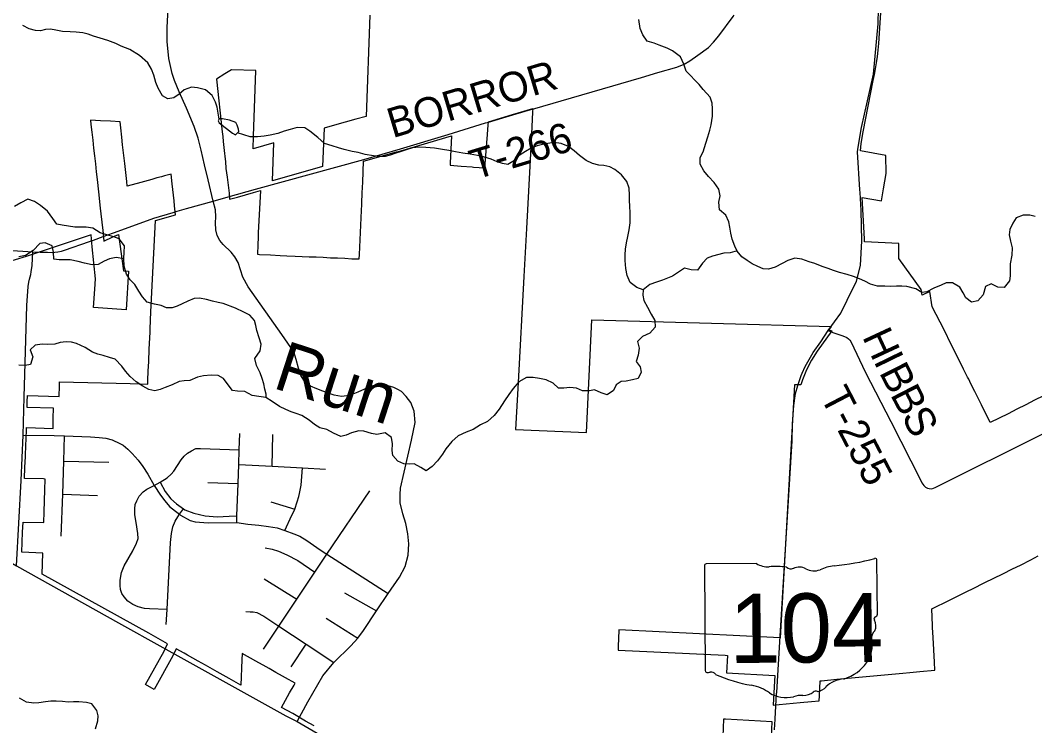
# Model space of a CAD drawing. Extents: x 114843 to 284848, y 317643 to 566895.
# Drawn here: x 189485 to 199714, y 338344 to 345452 of the extents above; entities that cross this region are included whole.
import ezdxf

# ---------------------------------------------------------------- set-up
doc = ezdxf.new("R2010")
doc.units = 0
for name, color, linetype in [('GM_X_City_Street', 7, 'Continuous'), ('GM_X_Corporation', 7, 'Continuous'), ('GM_X_Minor_Lake', 7, 'Continuous'), ('GM_X_Minor_River', 7, 'Continuous'), ('GM_X_Minor_River_Text', 7, 'Continuous'), ('GM_X_State_Location', 7, 'Continuous'), ('GM_X_State_Route', 7, 'Continuous'), ('GM_X_State_Shield', 7, 'Continuous'), ('GM_X_Township_Road', 7, 'Continuous'), ('GM_X_Township_Road_Text', 7, 'Continuous')]:
    doc.layers.add(name, color=color, linetype=linetype)

msp = doc.modelspace()

# ---------------------------------------------------------------- linework, layer by layer
at = {"layer": 'GM_X_City_Street'}
for p, q in [((189513, 341272), (189827, 341267)), ((192026, 340959), (192030, 341279)), ((189925, 341008), (190377, 340998)), ((191376, 340796), (191681, 340785)), ((189914, 340676), (190265, 340663)), ((192577, 340073), (193008, 340709)), ((192011, 340599), (192252, 340526)), ((191944, 339825), (192273, 339619)), ((192755, 339682), (193078, 339500)), ((192570, 339426), (192887, 339225)), ((192218, 338936), (192369, 339165))]:
    msp.add_line(p, q, dxfattribs=at)
for points in [[(191430, 343630), (191381, 343845), (191343, 343996), (191310, 344143), (191278, 344263), (191238, 344381), (191160, 344565), (191087, 344730), (191039, 344846), (191016, 344917), (190982, 345066), (190965, 345240), (190965, 345379), (190980, 345638)], [(192276, 338385), (192386, 338584), (192535, 338846), (192646, 338980), (192818, 339147), (192887, 339225), (192945, 339302), (193078, 339500), (193194, 339675), (193309, 339839), (193366, 339949), (193396, 340063), (193404, 340178), (193394, 340278), (193371, 340382), (193341, 340479), (193317, 340590), (193314, 340672), (193320, 340737), (193430, 341222), (193465, 341400), (193457, 341513), (193422, 341602), (193377, 341660), (193328, 341712), (193291, 341731), (193250, 341753), (193193, 341769), (193137, 341777), (193076, 341777), (193017, 341762), (192888, 341705), (192805, 341671), (192723, 341660), (192650, 341676), (192535, 341716), (192476, 341738), (192410, 341764), (192357, 341806), (192313, 341871), (192290, 341947), (192267, 342035), (192242, 342111), (192122, 342287), (191784, 342767), (191730, 342862), (191682, 343013), (191648, 343070), (191611, 343114), (191531, 343194), (191498, 343232), (191470, 343284), (191458, 343342), (191454, 343411), (191457, 343473), (191453, 343542), (191430, 343630)], [(189357, 343135), (189610, 343119)], [(189827, 341267), (189931, 341266), (190194, 341253), (190280, 341248), (190346, 341240), (190413, 341223), (190490, 341188), (190521, 341169), (190568, 341129), (190614, 341086), (190672, 341019), (190722, 340957), (190771, 340880), (190836, 340765), (190900, 340667), (190942, 340611), (190991, 340551), (191050, 340505), (191091, 340474), (191102, 340465), (191199, 340413), (191250, 340399), (191380, 340389), (191668, 340390), (191781, 340374), (191889, 340363), (191987, 340351), (192076, 340336), (192154, 340310), (192244, 340278), (192305, 340253), (192376, 340209), (192510, 340116), (192577, 340073), (193194, 339675)], [(189898, 340254), (189914, 340676), (189925, 341008), (189931, 341266)], [(191668, 340390), (191670, 340459), (191681, 340785), (191687, 340977), (191692, 341125), (191698, 341287)], [(190836, 340765), (190895, 340799), (190966, 340841), (191005, 340877), (191034, 340910), (191108, 341024), (191136, 341059), (191171, 341090), (191210, 341114), (191256, 341137), (191302, 341137), (191692, 341125)], [(191687, 340977), (192026, 340959), (192330, 340942), (192561, 340930)], [(192154, 340310), (192223, 340465), (192246, 340510), (192252, 340526), (192278, 340599), (192292, 340655), (192301, 340684), (192318, 340768), (192330, 340942)], [(190965, 339516), (190787, 339520), (190737, 339526), (190673, 339542), (190620, 339566), (190569, 339600), (190531, 339642), (190510, 339675), (190496, 339717), (190491, 339755), (190493, 339811), (190506, 339887), (190534, 339954), (190619, 340105), (190658, 340184), (190672, 340230), (190670, 340282), (190654, 340391), (190640, 340469), (190639, 340528), (190644, 340572), (190659, 340611), (190683, 340656), (190723, 340699), (190760, 340726), (190836, 340765)], [(190895, 340799), (190945, 340705), (191002, 340631), (191059, 340581), (191130, 340530), (191144, 340519), (191235, 340484), (191350, 340458), (191470, 340450), (191592, 340455), (191670, 340459)], [(190957, 339362), (190965, 339516), (191001, 340190), (191010, 340280), (191024, 340347), (191048, 340405), (191074, 340450), (191091, 340474), (191130, 340530)], [(191955, 340136), (192026, 340123), (192088, 340101), (192171, 340066), (192284, 340008), (192456, 339892)], [(191937, 339116), (192091, 339347), (192273, 339619), (192456, 339892), (192577, 340073)], [(191760, 339493), (191804, 339492), (191834, 339491), (191870, 339485), (191940, 339447), (192091, 339347), (192369, 339165), (192646, 338980)]]:
    msp.add_lwpolyline(points, dxfattribs=at)
at = {"layer": 'GM_X_Corporation'}
for points in [[(199802, 341667), (199713, 341623), (199623, 341578), (199534, 341533), (199445, 341488), (199355, 341443), (199266, 341399), (199177, 341577), (199109, 341711), (199071, 341788), (199048, 341835), (199042, 341845), (199036, 341857), (198997, 341936), (198934, 342061), (198872, 342184), (198801, 342332), (198678, 342565), (198655, 342718), (198578, 342681), (198570, 342738), (198345, 343051), (198343, 343203), (197998, 343220), (197997, 343251), (197983, 343488), (197973, 343666), (198168, 343633), (198188, 343753), (198215, 343909), (198213, 344091), (197956, 344135), (197963, 344212), (197984, 344327), (198086, 344846), (198097, 344905), (198108, 344964), (198118, 345023), (198128, 345087), (198136, 345152), (198142, 345217), (198246, 346829)], [(193009, 345503), (192971, 344484), (192867, 344455), (192760, 344425), (192654, 344395), (192549, 344365), (192545, 344288), (192532, 343979), (192028, 343835), (192040, 344217), (191936, 344187), (191832, 344158), (191837, 344283), (191859, 344946), (191616, 344953), (191548, 344911), (191462, 344858), (191521, 344328), (191526, 344281), (191532, 344231), (191542, 344141), (191552, 344051), (191554, 344030), (191559, 343960), (191572, 343871), (191587, 343736), (191590, 343709), (191596, 343648), (191676, 343671), (191837, 343717), (191906, 343736), (191885, 343311), (191884, 343280), (191879, 343176), (191876, 343108), (191876, 343094), (191898, 343093), (192008, 343088), (192104, 343083), (192174, 343080), (192258, 343076), (192328, 343073), (192398, 343070), (192468, 343067), (192538, 343064), (192613, 343060), (192683, 343057), (192758, 343054), (192828, 343050), (192902, 343047), (192904, 343091), (192908, 343165), (192911, 343239), (192915, 343313), (192918, 343387), (192922, 343461), (192925, 343535), (192928, 343596), (192928, 343610), (192933, 343713), (192938, 343821), (192945, 344031), (193279, 344125), (193288, 344127), (193504, 344189), (193832, 344289), (193819, 344013), (193818, 343991), (193931, 343983), (194042, 343974), (194055, 343973), (194168, 343964), (194196, 344300), (194203, 344397), (194206, 344430), (194449, 344503), (194653, 344562), (194651, 344528), (194640, 344303), (194622, 343981), (194589, 343355), (194562, 342869), (194505, 341802), (194480, 341329), (195193, 341299), (195248, 342433), (197662, 342368), (197637, 342332), (197668, 342323), (197521, 342119), (197462, 342027), (197413, 341930), (197392, 341880), (197373, 341828), (197356, 341777), (197293, 341780), (197146, 339230), (195521, 339310), (195521, 339310), (195518, 339220), (195515, 339150), (195513, 339106), (196591, 339053), (196615, 339051), (196605, 338878), (197094, 338850), (197091, 338791), (197081, 338616), (197077, 338550), (197138, 338556), (197349, 338577), (197462, 338587), (197541, 338595), (197544, 338646), (197552, 338795), (197564, 338796), (197719, 338811), (197825, 338821), (197866, 338825), (198124, 338850), (198274, 338864), (198383, 338874), (198453, 338881), (198555, 338891), (198706, 338903), (198702, 338983), (198695, 339107), (198689, 339232), (198684, 339332), (198683, 339355), (198677, 339522), (198856, 339610), (199035, 339698), (199086, 339723), (199212, 339786), (199392, 339874), (199491, 339923), (199570, 339963), (199674, 340016), (199749, 340054)], [(192448, 338343), (192362, 338391), (192232, 338466), (192119, 338528), (192201, 338674), (192246, 338753), (192256, 338772), (192158, 338827), (192130, 338843), (192062, 338881), (191995, 338919), (191963, 338936), (191859, 338994), (191723, 339071), (191720, 339008), (191710, 338753), (191685, 338767), (191592, 338819), (191470, 338887), (191352, 338953), (191280, 338993), (191172, 339054), (191136, 339074), (191057, 339118), (191022, 339048), (190834, 338709), (190746, 338758), (190935, 339096), (190969, 339168), (190780, 339275), (189705, 339872), (189712, 340083), (189502, 340092), (189505, 340193), (189509, 340294), (189513, 340395), (189723, 340390), (189726, 340500), (189730, 340610), (189734, 340720), (189737, 340829), (189719, 340830), (189528, 340835), (189532, 340945), (189536, 341055), (189540, 341178), (189544, 341225), (189547, 341337), (189547, 341347), (189815, 341340), (189818, 341443), (189821, 341543), (189554, 341550), (189555, 341606), (189557, 341670), (189877, 341662), (189881, 341768), (189882, 341809), (190594, 341792), (190770, 341787), (190772, 341825), (190776, 341915), (190780, 342014), (190786, 342137), (190793, 342308), (190795, 342344), (190803, 342514), (190847, 343435), (191050, 343493), (191044, 343553), (191041, 343581), (191035, 343634), (191016, 343803), (191005, 343903), (190940, 343885), (190909, 343876), (190863, 343863), (190812, 343849), (190736, 343827), (190699, 343817), (190564, 343779), (190558, 343829), (190538, 344009), (190526, 344118), (190517, 344198), (190509, 344276), (190498, 344367), (190492, 344429), (190395, 344434), (190294, 344440), (190193, 344446), (190198, 344403), (190207, 344324), (190213, 344271), (190216, 344244), (190224, 344165), (190233, 344085), (190242, 344006), (190251, 343926), (190260, 343847), (190273, 343724), (190292, 343558), (190314, 343360), (190316, 343338), (190328, 343226), (190419, 343270), (190477, 343292), (190525, 342927), (190576, 342925), (190553, 342533), (190224, 342557), (190236, 342742), (190244, 342847), (190211, 343169), (190199, 343289), (189545, 343072), (189322, 343005)], [(197059, 338235), (197068, 338382), (196595, 338408), (196576, 338409), (196569, 338234)]]:
    msp.add_lwpolyline(points, dxfattribs=at)
at = {"layer": 'GM_X_Minor_Lake'}
for points in [[(191688, 344331), (191686, 344355), (191672, 344396), (191660, 344422), (191596, 344446), (191524, 344460), (191492, 344460), (191480, 344438), (191490, 344418), (191626, 344315), (191656, 344299)], [(191656, 344299), (191688, 344331)]]:
    msp.add_lwpolyline(points, dxfattribs=at)
at = {"layer": 'GM_X_Minor_River'}
for points in [[(196399, 344213), (196417, 344279), (196438, 344345), (196450, 344399), (196464, 344487), (196466, 344559), (196460, 344618), (196440, 344678), (196372, 344756), (196330, 344806), (196198, 344939), (196174, 345009), (196142, 345083), (196063, 345145), (196009, 345171), (195927, 345203), (195875, 345220), (195806, 345242), (195763, 345304), (195735, 345370), (195721, 345460)], [(191490, 344456), (191470, 344576), (191455, 344626), (191421, 344695), (191351, 344751), (191273, 344771), (191213, 344777), (191137, 344753), (191086, 344709), (191032, 344671), (190974, 344661), (190920, 344691), (190876, 344767), (190852, 344826), (190833, 344898), (190807, 344960), (190771, 345022), (190687, 345098), (190591, 345157), (190503, 345193), (190447, 345217), (190369, 345247), (190289, 345273), (190223, 345293), (190169, 345312), (190115, 345326), (190049, 345334), (189987, 345336), (189909, 345340), (189845, 345352), (189791, 345364), (189739, 345358), (189688, 345346), (189638, 345348), (189574, 345366), (189510, 345399)], [(195765, 342737), (195703, 342759), (195633, 342811), (195605, 342879), (195591, 342951), (195585, 343031), (195585, 343090), (195589, 343146), (195599, 343208), (195611, 343274), (195623, 343342), (195634, 343410), (195634, 343514), (195632, 343577), (195628, 343639), (195628, 343689), (195624, 343759), (195600, 343827), (195548, 343895), (195480, 343949), (195428, 343976), (195370, 343990), (195318, 343992), (195256, 344010), (195190, 344040), (195124, 344090), (195070, 344138), (195012, 344181), (194938, 344209), (194866, 344219), (194804, 344211), (194750, 344201), (194696, 344187), (194636, 344163), (194578, 344131), (194514, 344089), (194450, 344029), (194400, 343999), (194346, 344009), (194292, 344027), (194232, 344051), (194154, 344076), (194096, 344090), (194020, 344102), (193947, 344114), (193875, 344128), (193807, 344140), (193741, 344150), (193661, 344162), (193573, 344171), (193507, 344173), (193439, 344167), (193385, 344151), (193327, 344131), (193273, 344113), (193215, 344093), (193163, 344079), (193099, 344079), (193047, 344087), (192963, 344101), (192891, 344119), (192833, 344131), (192751, 344150), (192693, 344168), (192631, 344186), (192551, 344212), (192485, 344270), (192405, 344334), (192353, 344369), (192277, 344373), (192207, 344353), (192147, 344335), (192083, 344311), (192006, 344295), (191944, 344285), (191876, 344279), (191804, 344279), (191676, 344319)], [(199717, 343475), (199665, 343487), (199598, 343487), (199528, 343461), (199492, 343409), (199464, 343345), (199456, 343289), (199470, 343227), (199486, 343159), (199482, 343084), (199466, 342998), (199465, 342876), (199461, 342826), (199407, 342760), (199343, 342762), (199275, 342796), (199219, 342768), (199193, 342686), (199139, 342626), (199075, 342612), (199019, 342654), (198991, 342706), (198957, 342764), (198883, 342805), (198821, 342805), (198771, 342783), (198695, 342753), (198627, 342717), (198575, 342709), (198515, 342745), (198425, 342769), (198373, 342773), (198320, 342773), (198258, 342771), (198204, 342773), (198130, 342774), (198058, 342794), (198000, 342822), (197946, 342848), (197886, 342870), (197824, 342890), (197744, 342912), (197684, 342931), (197630, 342951), (197570, 342971), (197496, 343001), (197440, 343019), (197366, 343045), (197296, 343055), (197226, 343033), (197168, 343001), (197096, 342965), (197028, 342943), (196974, 342947), (196922, 342970), (196866, 342998), (196814, 343030), (196762, 343068), (196714, 343126), (196690, 343176), (196664, 343246), (196648, 343307), (196638, 343367), (196630, 343421), (196600, 343487), (196534, 343541), (196527, 343619), (196543, 343684), (196529, 343750), (196481, 343818), (196423, 343878), (196377, 343936), (196341, 344002), (196341, 344069), (196371, 344127), (196399, 344213)], [(191964, 341648), (191964, 341684), (191952, 341734), (191941, 341788), (191925, 341844), (191905, 341898), (191867, 341974), (191851, 342043), (191903, 342121), (191913, 342187), (191895, 342253), (191871, 342325), (191861, 342375), (191845, 342427), (191800, 342479), (191738, 342510), (191656, 342550), (191532, 342598), (191479, 342608), (191423, 342622), (191361, 342638), (191291, 342651), (191237, 342649), (191173, 342623), (191117, 342595), (191067, 342571), (191015, 342555), (190959, 342555), (190905, 342577), (190837, 342593), (190765, 342611), (190717, 342665), (190679, 342724), (190639, 342788), (190593, 342838), (190557, 342894), (190533, 342974), (190528, 343054), (190534, 343113), (190536, 343181), (190482, 343249), (190428, 343271), (190358, 343291), (190292, 343309), (190216, 343359), (190148, 343368), (190096, 343366), (190034, 343368), (189970, 343376), (189908, 343386), (189854, 343398), (189812, 343454), (189758, 343528), (189690, 343585), (189630, 343627), (189560, 343649), (189492, 343611), (189426, 343575)], [(190528, 343049), (190451, 343061), (190383, 343049), (190331, 343025), (190269, 342991), (190211, 342987), (190131, 343003), (190067, 343023), (189987, 343037), (189929, 343039), (189877, 343039), (189823, 343045), (189821, 343116), (189805, 343180), (189737, 343210), (189683, 343202), (189615, 343132), (189539, 343082), (189469, 343070)], [(196713, 343128), (196642, 343110), (196578, 343104), (196466, 343076), (196410, 343056), (196363, 343004), (196315, 342934), (196249, 342936), (196183, 342955), (196063, 342875), (195959, 342835), (195901, 342813), (195833, 342789), (195765, 342737), (195763, 342683), (195772, 342628), (195808, 342560), (195846, 342490), (195884, 342426), (195888, 342360), (195832, 342298), (195758, 342266), (195708, 342214), (195726, 342148), (195716, 342077), (195694, 342015), (195735, 341959), (195745, 341905), (195715, 341843), (195659, 341829), (195595, 341817), (195545, 341811), (195493, 341779), (195467, 341723), (195403, 341677), (195343, 341697), (195275, 341727), (195223, 341717), (195155, 341717), (195093, 341746), (195027, 341752), (194967, 341744), (194913, 341744), (194859, 341794), (194787, 341828), (194719, 341842), (194657, 341854), (194590, 341854), (194512, 341810), (194456, 341740), (194412, 341680), (194368, 341618), (194314, 341534), (194262, 341470), (194196, 341408), (194125, 341374), (194051, 341330), (193981, 341302), (193901, 341264), (193837, 341206), (193775, 341134), (193743, 341080), (193691, 341012), (193638, 340954), (193576, 340912), (193524, 340946), (193456, 340984), (193406, 340980), (193354, 340984), (193292, 341008), (193240, 341065), (193236, 341117), (193239, 341183), (193229, 341249), (193165, 341295), (193079, 341279), (193025, 341287), (192949, 341312), (192898, 341314), (192824, 341294), (192770, 341272), (192716, 341258), (192644, 341292), (192576, 341328), (192504, 341346), (192452, 341380), (192398, 341422), (192324, 341471), (192268, 341489), (192216, 341507), (192162, 341531), (192098, 341559), (192026, 341611), (191960, 341650), (191892, 341660), (191822, 341670), (191750, 341712), (191676, 341714), (191624, 341720), (191572, 341792), (191534, 341843)], [(191534, 341843), (191480, 341873), (191410, 341877), (191332, 341869), (191272, 341855), (191196, 341823), (191136, 341819), (191086, 341811), (191016, 341779), (190946, 341753), (190894, 341733), (190840, 341717), (190782, 341731), (190720, 341764), (190654, 341810), (190592, 341864), (190546, 341918), (190510, 341968), (190442, 342036), (190384, 342055), (190320, 342073), (190266, 342087), (190214, 342109), (190140, 342155), (190052, 342195), (190000, 342209), (189948, 342212), (189888, 342204), (189832, 342190), (189758, 342184), (189704, 342188), (189636, 342178), (189583, 342130), (189613, 342060), (189587, 341984), (189535, 341972), (189471, 341978)], [(190244, 338311), (190266, 338393), (190270, 338443), (190258, 338497), (190206, 338563), (190154, 338576), (190076, 338584), (190022, 338584), (189968, 338582), (189910, 338588), (189846, 338590), (189792, 338590), (189740, 338584), (189672, 338574), (189622, 338570), (189548, 338582), (189478, 338621)]]:
    msp.add_lwpolyline(points, dxfattribs=at)
at = {"layer": 'GM_X_State_Route'}
for p, q in [((190924, 339131), (191012, 339082)), ((197089, 338302), (197095, 338408))]:
    msp.add_line(p, q, dxfattribs=at)
for points in [[(197953, 343717), (197951, 343744), (197928, 344125), (197932, 344173), (197966, 344372), (198088, 344909), (198134, 345418), (198137, 345572), (198153, 345862), (198182, 346112), (198188, 346425), (198241, 347270)], [(197632, 342325), (197758, 342502), (197823, 342631), (197916, 342824), (197956, 342982), (197972, 343231), (197964, 343537), (197953, 343717)], [(197360, 341872), (197369, 341897), (197398, 341965), (197481, 342106), (197556, 342211), (197632, 342325)], [(197326, 341772), (197338, 341813), (197360, 341872)], [(186181, 341793), (186185, 341790), (187056, 341297), (188324, 340593), (188601, 340426), (189267, 340059), (189447, 339954), (190474, 339381), (190924, 339131)], [(197147, 339247), (197268, 341214), (197272, 341387), (197285, 341569), (197303, 341691), (197326, 341772)], [(197111, 338667), (197112, 338678), (197147, 339247)], [(191012, 339082), (192164, 338442), (192276, 338385), (193600, 337613), (193667, 337577), (193729, 337559), (193801, 337529), (193873, 337505), (193923, 337491)], [(197095, 338408), (197096, 338413), (197111, 338667)]]:
    msp.add_lwpolyline(points, dxfattribs=at)
at = {"layer": 'GM_X_State_Shield'}
for p, q in [((198127, 339460), (198123, 340013)), ((196383, 339956), (196391, 338899)), ((196910, 339978), (196400, 339974)), ((198127, 339460), (198127, 339460))]:
    msp.add_line(p, q, dxfattribs=at)
for centre, major_axis, ratio, start_param, end_param in [((197493, 341423), (1846, 13), 0.800001, 4.814395, 5.042369), ((198104, 340015), (19.4, 0.1), 0.8, 6.141152, 7.989035), ((196403, 339958), (20.2, 0.1), 0.8, 1.712693, 3.28349), ((197030, 340101), (196, 1), 0.8, 4.042523, 4.731795), ((197100, 339386), (702, 5), 0.8, 1.404758, 1.657858), ((197255, 339970), (56.4, 0.4), 0.8, 3.836095, 5.185415), ((197339, 339848), (117, 1), 0.8, 0.950623, 2.079405), ((197489, 340017), (141, 1), 0.8, 4.081561, 5.145723), ((197741, 339661), (371, 3), 0.8, 1.699011, 2.107814), ((198123, 339419), (30, 0.2), 0.8, 1.883978, 3.671073), ((197933, 339348), (180, 1), 0.8, 5.934695, 6.695948), ((198106, 339458), (20.7, 0.1), 0.8, 5.05454, 6.418171), ((198198, 339229), (131, 1), 0.8, 2.387724, 3.262537), ((197613, 339155), (462, 3), 0.8, 5.101753, 6.440018), ((196411, 338897), (20.3, 0.1), 0.8, 3.00124, 4.508301), ((196413, 339005), (155, 1), 0.8, 4.665946, 4.897461), ((196446, 338839), (56, 0.4), 0.8, 0.519207, 1.627899), ((197146, 339793), (1333, 10), 0.8, 4.195996, 4.488959), ((197811, 338613), (253, 2), 0.8, 1.647645, 2.488434), ((196758, 338427), (417, 3), 0.8, 0.823519, 1.323588), ((197206, 338839), (265, 2), 0.8, 4.026481, 4.996735), ((197379, 338761), (141, 1), 0.8, 4.691044, 5.507374), ((197507, 338659), (39.7, 0.3), 0.8, 1.147584, 2.315152), ((197490, 338805), (149, 1), 0.8, 4.937069, 5.64225), ((197362, 338475), (217, 2), 0.8, 1.495662, 1.94098)]:
    msp.add_ellipse(centre, major_axis=major_axis, ratio=ratio, start_param=start_param, end_param=end_param, dxfattribs=at)
at = {"layer": 'GM_X_Township_Road'}
for p, q in [((191430, 343630), (191582, 343673)), ((190222, 343238), (190321, 343274)), ((190321, 343274), (190471, 343328))]:
    msp.add_line(p, q, dxfattribs=at)
for points in [[(194634, 344553), (194649, 344558), (195750, 344877), (195915, 344925), (196106, 344981), (196178, 345009), (196237, 345043), (196318, 345102), (196424, 345179), (196476, 345231), (196530, 345297), (196674, 345492), (196683, 345505)], [(194177, 344418), (194207, 344427), (194450, 344500), (194634, 344553)], [(193318, 344158), (193799, 344301), (194177, 344418)], [(191582, 343673), (191857, 343751), (192948, 344048), (193318, 344158)], [(191025, 343515), (191066, 343527), (191161, 343555), (191430, 343630)], [(190471, 343328), (190830, 343458), (191025, 343515)], [(189610, 343119), (189685, 343116), (189758, 343114), (189806, 343113), (189833, 343115), (189865, 343118), (189899, 343126), (189932, 343134), (190182, 343224), (190222, 343238)], [(189447, 339954), (189494, 340814), (189513, 341272), (189523, 341654), (189552, 342578), (189564, 342771), (189570, 342813), (189577, 342845), (189591, 342891), (189596, 342918), (189604, 342982), (189610, 343119)], [(197632, 342325), (197678, 342305), (197780, 342272), (197819, 342254), (197836, 342241), (197849, 342228), (197859, 342214), (198008, 341904), (198264, 341410), (198564, 340815), (198576, 340790), (198595, 340763), (198613, 340748), (198632, 340738), (198651, 340733), (198676, 340732), (198709, 340743), (198925, 340850), (199579, 341179), (200674, 341726)]]:
    msp.add_lwpolyline(points, dxfattribs=at)

# ---------------------------------------------------------------- texts
at = {"layer": 'GM_X_Minor_River_Text'}
msp.add_text('Run', height=500, rotation=342.0322, dxfattribs=at).set_placement((192018, 341752))
at = {"layer": 'GM_X_State_Location'}
for s, rotation, p in [('104', 0.4132, (196885, 339288)), ('s', 0.4131, (197238, 339363)), ('r', 0.4131, (197238, 339363))]:
    msp.add_text(s, height=1, rotation=rotation, dxfattribs=at).set_placement(p)
at = {"layer": 'GM_X_State_Shield'}
msp.add_text('104', height=696.1, rotation=0.4131, dxfattribs=at).set_placement((196636, 338975))
at = {"layer": 'GM_X_Township_Road_Text'}
for s, rotation, p in [('BORROR', 16.6787, (193239, 344263)), ('T-266', 16.7407, (194072, 343844)), ('H', 294.9227, (197971, 342264)), ('I', 296.0124, (198085, 342019)), ('B', 296.9101, (198141, 341904)), ('T-255', 297.4801, (197544, 341664)), ('B', 297.2726, (198253, 341682)), ('S', 297.2738, (198366, 341463))]:
    msp.add_text(s, height=300, rotation=rotation, dxfattribs=at).set_placement(p)

doc.saveas('drawing.dxf')
